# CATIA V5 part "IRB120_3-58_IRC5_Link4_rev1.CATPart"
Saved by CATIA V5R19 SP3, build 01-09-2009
Part number: Link4
Definition: design
Nomenclature: Link4
Source: Unknown
Bounding box of the stored display mesh (mm): x 148.6 to 342.08, y -62.57 to 62.228, z 584.045 to 689.95
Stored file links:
  Z:\Projects\ABB_Robotics\ABB LIB\V5\V5PARTS\ABB\120\IRB120_3-58_IRC5_Link4_rev1.CATPart
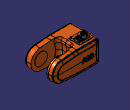
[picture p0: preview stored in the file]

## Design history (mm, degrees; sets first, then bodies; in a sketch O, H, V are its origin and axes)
Body1 "NONE" (main body)
  Solid1: solid without history
Body2 "NONE"
  Solid2: solid without history
Body3 "NONE"
  Solid3: solid without history
Body4 "NONE"
  Solid4: solid without history
Body5 "NONE"
  Solid5: solid without history
Body6 "NONE"
  Solid6: solid without history
Body7 "NONE"
  Solid7: solid without history
Body8 "NONE"
  Solid8: solid without history
Body9 "NONE"
  Solid9: solid without history
Body10 "NONE"
  Solid10: solid without history
Body11 "NONE"
  Solid11: solid without history
Body12 "NONE"
  Solid12: solid without history
Body13 "NONE"
  Solid13: solid without history
Body14 "NONE"
  Solid14: solid without history
Body15 "NONE"
  Solid15: solid without history
Body16 "NONE"
  Solid16: solid without history
Body17 "NONE"
  Solid17: solid without history
Body18 "NONE"
  Solid18: solid without history
Body19 "NONE"
  Solid19: solid without history
Body20 "NONE"
  Solid20: solid without history
Body21 "NONE"
  Solid21: solid without history
Body22 "NONE"
  Solid22: solid without history
Body23 "NONE"
  Solid23: solid without history
Body24 "NONE"
  Solid24: solid without history
Body25 "NONE"
  Solid25: solid without history
Body26 "NONE"
  Solid26: solid without history
Body27 "NONE"
  Solid27: solid without history
Body28 "NONE"
  Solid28: solid without history
Body29 "NONE"
  Solid29: solid without history
Body30 "NONE"
  Solid30: solid without history
Body31 "NONE"
  Solid31: solid without history
Body32 "NONE"
  Solid32: solid without history
Body33 "NONE"
  Solid33: solid without history
Body34 "NONE"
  Solid34: solid without history
Body35 "NONE"
  Solid35: solid without history
Body36 "NONE"
  Solid36: solid without history
Body37 "NONE"
  Solid37: solid without history
Body38 "NONE"
  Solid38: solid without history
